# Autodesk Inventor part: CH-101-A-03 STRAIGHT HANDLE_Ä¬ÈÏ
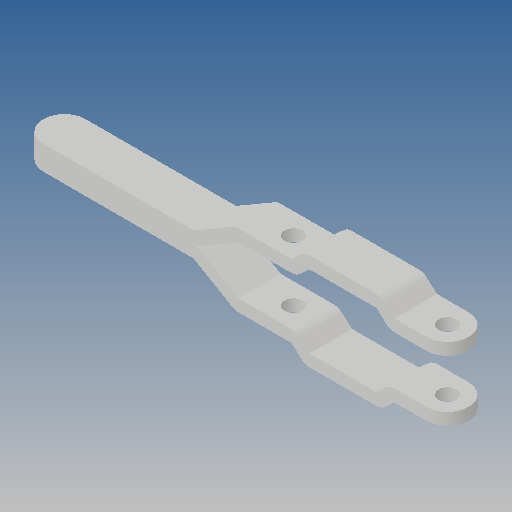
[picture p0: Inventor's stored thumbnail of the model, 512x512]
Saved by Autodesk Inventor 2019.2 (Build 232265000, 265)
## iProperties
Created: 2010-06
Part Number: CH-101-A-03 STRAIGHT HANDLE_Ä¬ÈÏ
Material: Ogólny
Document SubType Name: Modeling
Designer: CADENGINEERING4
Density: 1 g/cm^3
Appearance: Domyślna
Author: CADENGINEERING4
Revision Number: ÈÎºÎ
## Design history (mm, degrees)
feature "NONE"
feature "NONE:1"
node "Bryła1"
node "Bryła2"
